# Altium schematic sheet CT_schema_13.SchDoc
size 386 x 278 mm
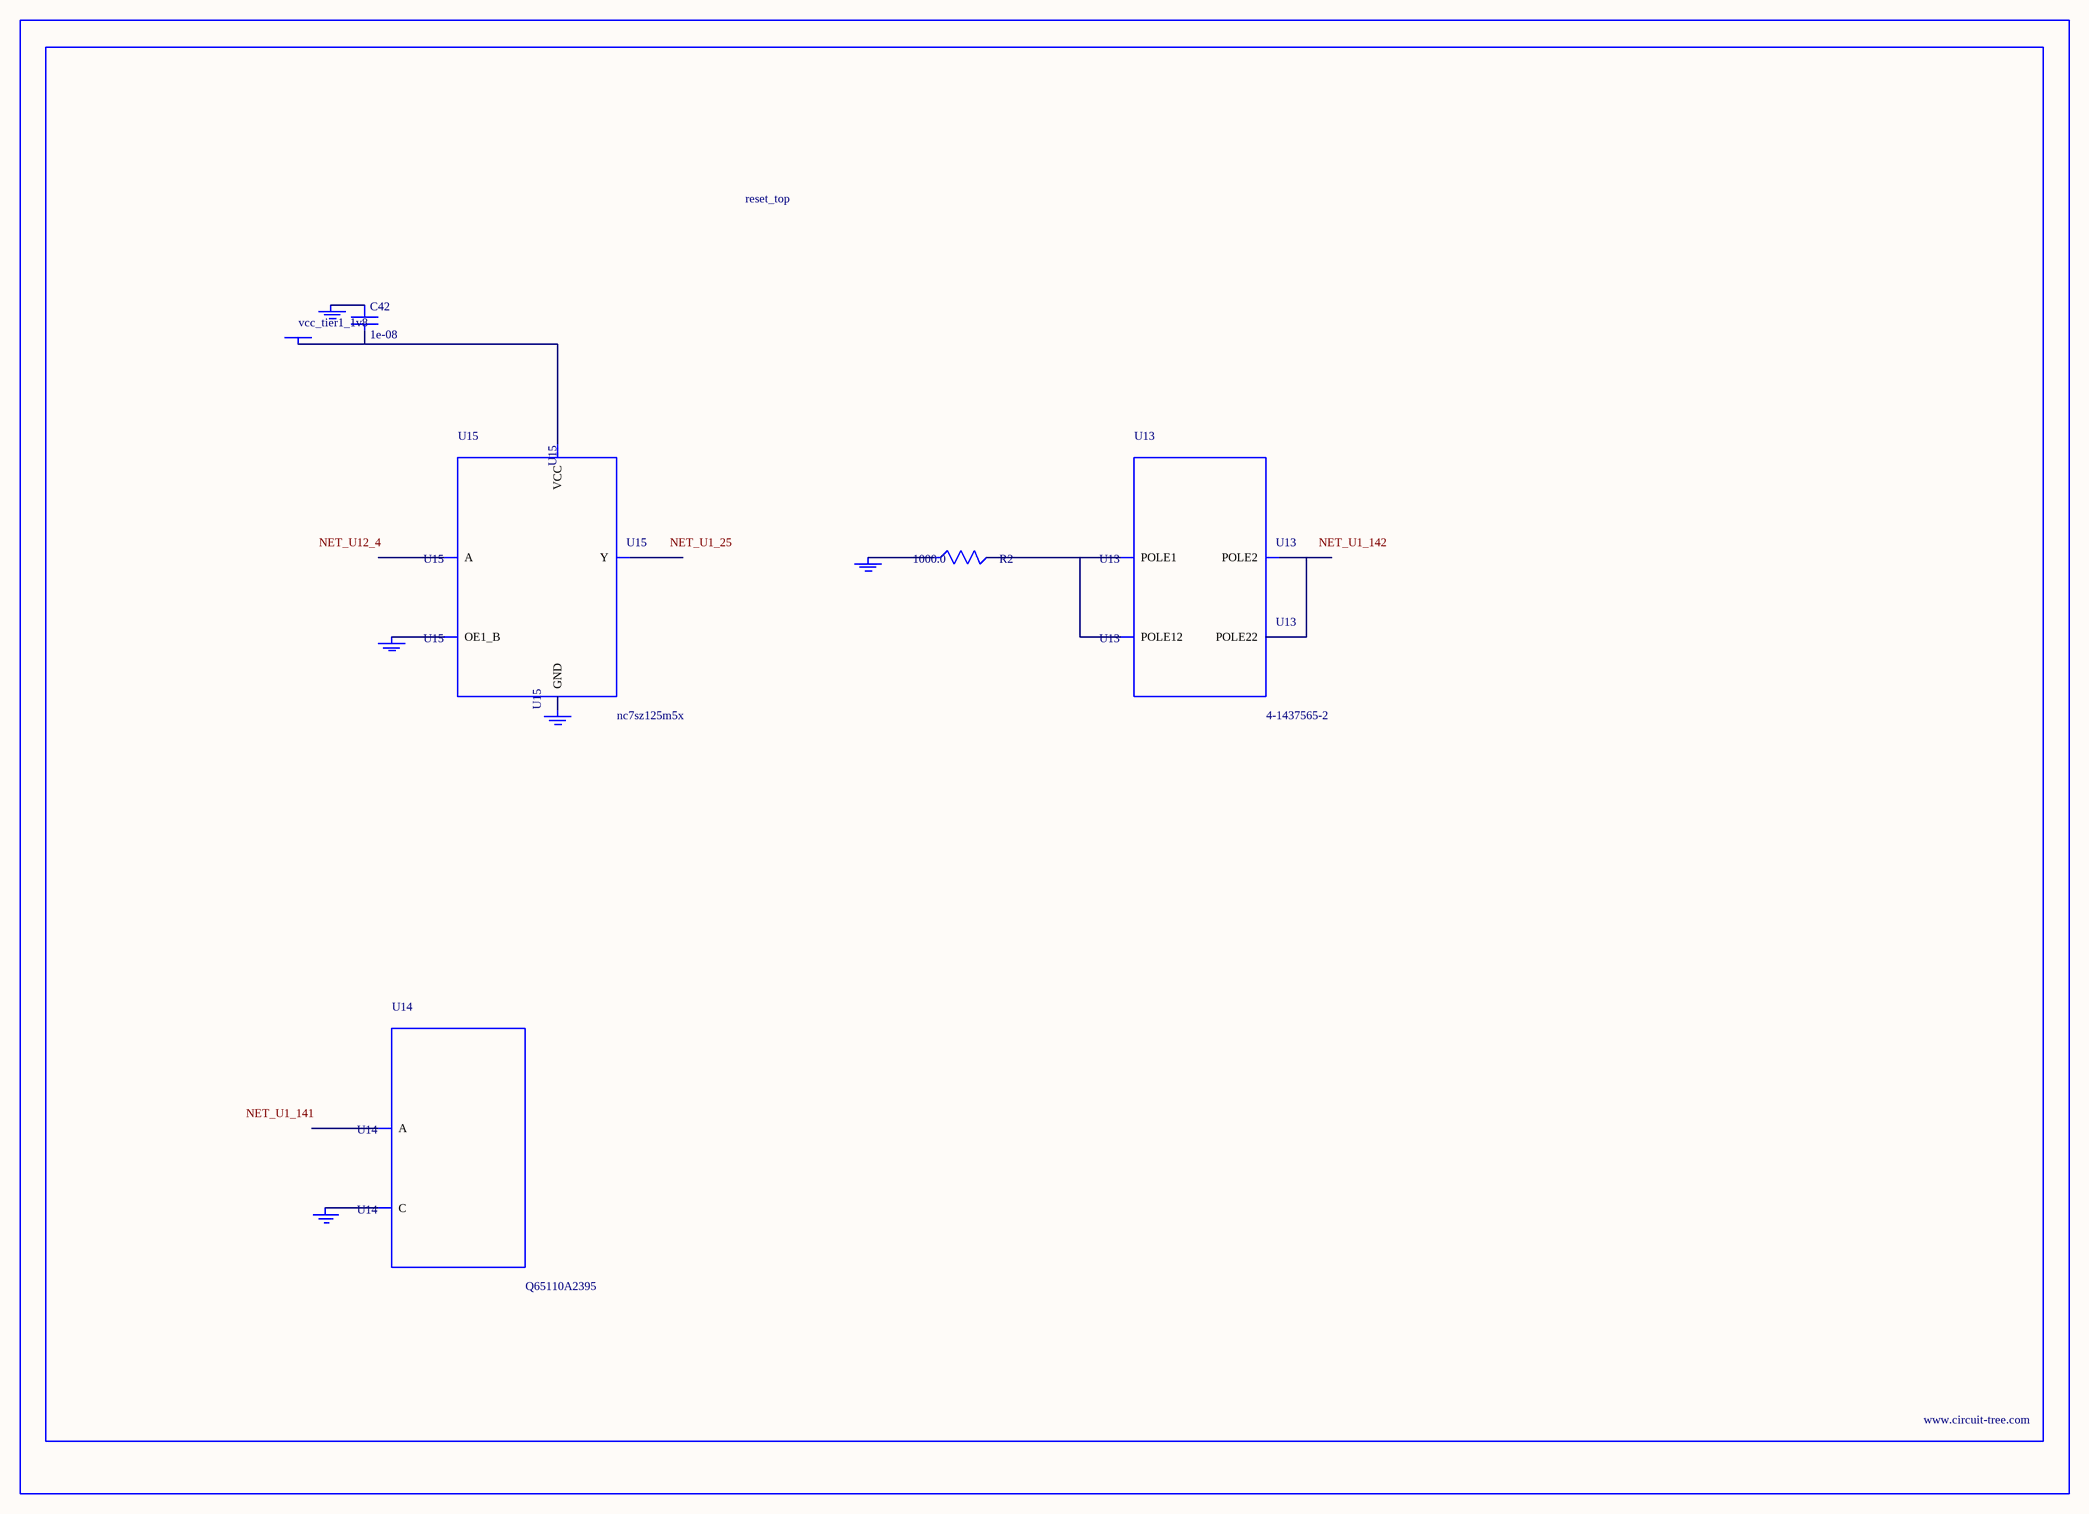
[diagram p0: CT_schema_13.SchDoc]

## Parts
BORDER12  (no value)
C42  1e-08  [C0402]
GND_INSTANCE_12_0  (no value)
GND_INSTANCE_12_1  (no value)
GND_INSTANCE_12_2  (no value)
GND_INSTANCE_12_3  (no value)
GND_INSTANCE_12_4  (no value)
POWER_INSTANCE_12_0  vcc_tier1_1v8
R2  1000.0  [R0603]
U13  4-1437565-2  [SW_4-1437565-2]
U14  Q65110A2395  [LGM67K-G1J2-24-Z]
U15  nc7sz125m5x  [NC7SZ125M5X]

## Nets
NetC42_1: C42.1 GND_INSTANCE_12_2.0(GND)
NetC42_2: C42.2 POWER_INSTANCE_12_0.0(PWR) U15.5(VCC)
NetGND_INSTANCE_12_0_0: GND_INSTANCE_12_0.0(GND) R2.1
NetGND_INSTANCE_12_1_0: GND_INSTANCE_12_1.0(GND) U14.C
NetGND_INSTANCE_12_3_0: GND_INSTANCE_12_3.0(GND) U15.1(OE1_B)
NetGND_INSTANCE_12_4_0: GND_INSTANCE_12_4.0(GND) U15.3(GND)
NetR2_2: R2.2 U13.1(POLE1) U13.2(POLE12)
NetU13_3: U13.3(POLE2) U13.4(POLE22)

Not connected (* = marked no-connect by the designer): U14 A; U15 2(A) 4(Y)

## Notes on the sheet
- Labels drawn without touching a wire or pin: NET_U1_25, NET_U1_141, NET_U1_142, NET_U12_4

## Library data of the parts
BORDER12 = BORDER_PAGE12
C42 = C0402C103K3RAC
GND_INSTANCE_12_0-GND_INSTANCE_12_4 = GND
POWER_INSTANCE_12_0 = PWR
R2 = RC0603JR-071KL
